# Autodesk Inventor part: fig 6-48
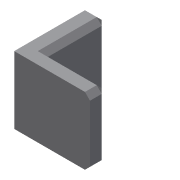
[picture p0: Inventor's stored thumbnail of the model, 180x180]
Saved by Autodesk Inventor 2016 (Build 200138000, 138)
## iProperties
Created: 2009-09
Part Number: fig 6-48
Document SubType Name: Modeling
Designer: Sham
Density: 1 g/cm^3
Material: Generic
Appearance: Default
Author: Sham
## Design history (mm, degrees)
sketch "Sketch1"
  geometry: L1 (1.789, 30)-(1.789, -5); L2 (1.789, -5)-(36.789, -5); L3 (36.789, -5)-(36.789, -15); L4 (36.789, -15)-(-8.211, -15); L5 (-8.211, -15)-(-8.211, 30); L6 (-8.211, 30)-(1.789, 30)
  constraints: 12 end point, 6 perpendicular
  dimensions: "d0" = 10 distance of L5.end L1.start; "d1" = 35 distance of L1.start L1.end; "d2" = 45 distance of L3.end L4.end; "d3" = 10 distance of L2.end L3.end (derived)
extrude "Extrusion1" new body sketch "Sketch1" distance "d4" = 40; taper "d5" = 0 deg
chamfer "Chamfer1" distance "d6" = 3; stored, may be unused: second distance "d7" = 2, angle "d8" = 45 deg
body "Solid1"
other parameters: "d1" = 35
